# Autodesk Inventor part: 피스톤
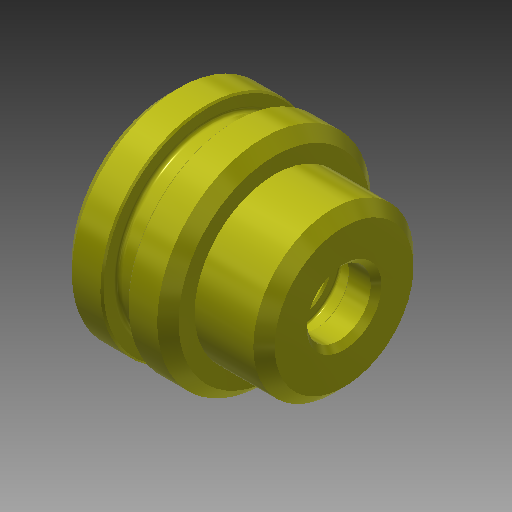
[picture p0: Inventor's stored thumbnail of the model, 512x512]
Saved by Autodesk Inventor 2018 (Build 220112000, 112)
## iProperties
Created: 2020-02
Part Number: 피스톤
Material: 강철, 탄소
Document SubType Name: Modeling
Designer: mduedu
Density: 1 g/cm^3
Appearance: 노란색
Author: mduedu
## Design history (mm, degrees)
sketch "스케치1"
  geometry: L1 (0, 0)-(20, 0); L2 (20, 0)-(20, 20); L3 (20, 20)-(0, 20); L4 (0, 20)-(0, 0); L5 (20, 0)-(33, 0); L6 (33, 0)-(33, 15); L7 (33, 15)-(20, 15); L8 (20, 15)-(20, 0)
  constraints: 16 end point, 4 parallel, 2 horizontal, 2 perpendicular
  dimensions: "d0" = 33 distance between parallel lines of L6 L4; "d2" = 20 distance of L2.end L3.end; "d3" = 40 diameter of L3 L1; "d4" = 30 diameter of L7 L5
revolve "회전1" sketch "스케치1" stored, may be unused: angle "d5" = 90 deg
sketch "스케치2"
  geometry: L1 (0, -20)-(0, 20) reference; L2 (0, 20)-(20, 20) reference; L3 (20, 20)-(20, 15) reference; L4 (20, 15)-(33, 15) reference; L5 (33, 15)-(33, -15) reference; L6 (33, -15)-(20, -15) reference; L7 (20, -15)-(20, -20) reference; L8 (20, -20)-(0, -20) reference; L9 (0, 0)-(20, 0); L10 (20, 0)-(20, 11); L11 (20, 11)-(0, 11); L12 (0, 11)-(0, 0); L13 (33, 0)-(20, 0); L14 (20, 0)-(20, 6); L15 (20, 6)-(33, 6); L16 (33, 6)-(33, 0)
  constraints: 16 end point, 4 parallel, 2 horizontal, 2 perpendicular, 1 midpoint, 1 point on line
  dimensions: "d6" = 22 diameter of L11 L9; "d8" = 12 diameter of L15 L13; "d9" = 20 distance of L10.end L11.end
revolve "회전2" sketch "스케치2" stored, may be unused: angle "d10" = 90 deg
chamfer "모따기1" distance "d11" = 2; stored, may be unused: second distance "d12" = 2, angle "d13" = 45 deg
sketch "스케치3"
  geometry: L1 (20, -11)-(20, -6) reference; L2 (20, -6)-(33, -6) reference; L3 (33, -6)-(33, -13) reference; L4 (33, -13)-(31, -15) reference; L5 (31, -15)-(20, -15) reference; L6 (20, -15)-(20, -18) reference; L7 (20, -18)-(18, -20) reference; L8 (18, -20)-(2, -20) reference; L9 (2, -20)-(0, -18) reference; L10 (0, -18)-(0, -11) reference; L11 (0, -11)-(20, -11) reference; L12 (20, 6)-(20, 11) reference; L13 (20, 11)-(0, 11) reference; L14 (0, 11)-(0, 18) reference; L15 (0, 18)-(2, 20) reference; L16 (2, 20)-(18, 20) reference; L17 (18, 20)-(20, 18) reference; L18 (20, 18)-(20, 15) reference; L19 (20, 15)-(31, 15) reference; L20 (31, 15)-(33, 13) reference; L21 (33, 13)-(33, 6) reference; L22 (33, 6)-(20, 6) reference; L23 (7.65, 20)-(12.35, 20); L24 (12.35, 20)-(12.35, 17); L25 (12.35, 17)-(7.65, 17); L26 (7.65, 17)-(7.65, 20); L27 (24.4, 6)-(27.6, 6); L28 (27.6, 6)-(27.6, 8); L29 (27.6, 8)-(24.4, 8); L30 (24.4, 8)-(24.4, 6); L31 (10, 17)-(10, 20); L32 (26, 6)-(26, 8); L33 (-6.6, 0)-(39.6, 0) reference; 1 further point
  constraints: 20 end point, 4 midpoint, 4 parallel, 2 horizontal, 2 perpendicular, 2 point on line
  dimensions: "d14" = 10 distance between parallel lines of L31 L14; "d15" = 7 distance between parallel lines of L32 L21; "d16" = 4.7 distance between parallel lines of L24 L26; "d17" = 34 diameter of L25 L33; "d18" = 16 diameter of L29 L33; "d19" = 3.2 distance of L28.end L29.end
revolve "회전3" sketch "스케치3" stored, may be unused: angle "d20" = 90 deg
fillet "모깎기1" dims "d21" = 0.8
fillet "모깎기2" dims "d22" = 0.4
chamfer "모따기2" distance "d23" = 0.3; stored, may be unused: second distance "d24" = 2, angle "d25" = 45 deg
chamfer "모따기3" distance "d26" = 0.3; stored, may be unused: second distance "d27" = 2, angle "d28" = 45 deg
chamfer "모따기4" distance "d29" = 1; stored, may be unused: second distance "d30" = 2, angle "d31" = 45 deg
node "솔리드1"
node "절단 모서리 투영1"
node "절단 모서리 투영2"
